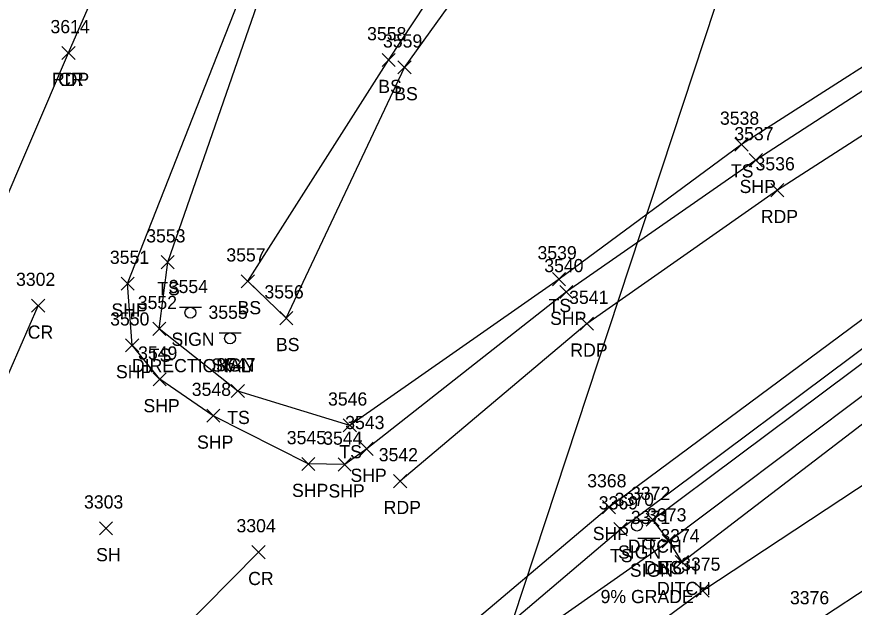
# Model space of a CAD drawing. Extents: x 1623612 to 1625808, y 621345 to 627748.
# Drawn here: x 1624984.7 to 1625111.7, y 626826.7 to 626916.3 of the extents above; entities that cross this region are included whole.
import ezdxf

# ---------------------------------------------------------------- set-up
doc = ezdxf.new("R2010")
doc.units = 0
for name, color, linetype in [('D_A', 7, 'Continuous'), ('D_I', 7, 'Continuous'), ('D_TIC', 7, 'Continuous'), ('DCP', 7, 'Continuous'), ('DD', 7, 'Continuous'), ('L_A', 7, 'Continuous'), ('L_I', 7, 'Continuous'), ('L_TIC', 7, 'Continuous'), ('LAWA', 7, 'Continuous'), ('LELB', 7, 'Continuous'), ('P_A', 7, 'Continuous'), ('P_I', 7, 'Continuous'), ('P_TIC', 7, 'Continuous'), ('PET', 7, 'Continuous'), ('PRC', 7, 'Continuous'), ('PSP', 7, 'Continuous'), ('S_A', 7, 'Continuous'), ('S_C', 7, 'Continuous'), ('S_I', 7, 'Continuous'), ('SSGN', 7, 'Continuous')]:
    doc.layers.add(name, color=color, linetype=linetype)

msp = doc.modelspace()

# ---------------------------------------------------------------- linework, layer by layer
at = {"layer": 'D_TIC'}
for points in [[(1625080.1, 626838.99), (1625082.1, 626840.99)], [(1625082.1, 626838.99), (1625080.1, 626840.99)], [(1625080.1, 626838.99), (1625082.1, 626840.99)], [(1625082.1, 626838.99), (1625080.1, 626840.99)], [(1625082.54, 626835.73), (1625084.54, 626837.73)], [(1625084.54, 626835.73), (1625082.54, 626837.73)], [(1625084.53, 626832.57), (1625086.53, 626834.57)], [(1625086.53, 626832.57), (1625084.53, 626834.57)]]:
    msp.add_lwpolyline(points, dxfattribs=at)
at = {"layer": 'DCP'}
msp.add_lwpolyline([(1625053.56, 626805.57), (1625095.39, 626932.35)], dxfattribs=at)
at = {"layer": 'DD'}
for points in [[(1625081.1, 626839.99), (1625120.07, 626869.1), (1625148.51, 626886.8), (1625173.75, 626902.4)], [(1625081.1, 626839.99), (1625083.54, 626836.73), (1625085.53, 626833.57), (1625123.95, 626862.95), (1625153.24, 626881.37), (1625160.13, 626885.56), (1625177.06, 626894.7), (1625176.09, 626897.9), (1625175.36, 626899.84), (1625173.75, 626902.4)]]:
    msp.add_lwpolyline(points, dxfattribs=at)
at = {"layer": 'L_TIC'}
for points in [[(1625040.06, 626908.7), (1625042.06, 626910.7)], [(1625042.06, 626908.7), (1625040.06, 626910.7)], [(1625042.48, 626907.59), (1625044.48, 626909.59)], [(1625044.48, 626907.59), (1625042.48, 626909.59)], [(1625093.57, 626895.89), (1625095.57, 626897.89)], [(1625095.57, 626895.89), (1625093.57, 626897.89)], [(1625006.56, 626878.04), (1625008.56, 626880.04)], [(1625008.56, 626878.04), (1625006.56, 626880.04)], [(1625018.71, 626875.15), (1625020.71, 626877.15)], [(1625020.71, 626875.15), (1625018.71, 626877.15)], [(1625065.91, 626875.48), (1625067.91, 626877.48)], [(1625067.91, 626875.48), (1625065.91, 626877.48)], [(1625024.54, 626869.55), (1625026.54, 626871.55)], [(1625026.54, 626869.55), (1625024.54, 626871.55)], [(1625024.54, 626869.55), (1625026.54, 626871.55)], [(1625026.54, 626869.55), (1625024.54, 626871.55)], [(1625005.28, 626867.94), (1625007.28, 626869.94)], [(1625007.28, 626867.94), (1625005.28, 626869.94)], [(1625017.18, 626858.5), (1625019.18, 626860.5)], [(1625019.18, 626858.5), (1625017.18, 626860.5)], [(1625034.19, 626853.3), (1625036.19, 626855.3)], [(1625036.19, 626853.3), (1625034.19, 626855.3)], [(1624997.21, 626837.69), (1624999.21, 626839.69)], [(1624999.21, 626837.69), (1624997.21, 626839.69)], [(1625075.24, 626837.55), (1625077.24, 626839.55)], [(1625077.24, 626837.55), (1625075.24, 626839.55)], [(1625082.54, 626835.73), (1625084.54, 626837.73)], [(1625084.54, 626835.73), (1625082.54, 626837.73)], [(1625087.69, 626828.26), (1625089.69, 626830.26)], [(1625089.69, 626828.26), (1625087.69, 626830.26)]]:
    msp.add_lwpolyline(points, dxfattribs=at)
at = {"layer": 'LAWA'}
msp.add_lwpolyline([(1625011.66, 626754.51), (1625041.42, 626781.36), (1625076.28, 626803.36), (1625105.24, 626824.17), (1625136.64, 626844.76), (1625156.9, 626876.93), (1625160.13, 626885.56)], dxfattribs=at)
at = {"layer": 'LELB'}
for points in [[(1625025.54, 626870.55), (1625019.71, 626876.15), (1625041.06, 626909.7), (1625061.93, 626941.31), (1625075.11, 626978.51), (1625096.76, 627007.08), (1625116.96, 627042.12), (1625139.15, 627072.88), (1625173.57, 627103.31), (1625198.3, 627138.01)], [(1625469.29, 627095.38), (1625429.94, 627072.01), (1625396.47, 627056.33), (1625363.17, 627036.91), (1625324.86, 627017.28), (1625282.83, 626996.93), (1625240.1, 626976.36), (1625200.92, 626956.72), (1625164.36, 626938.31), (1625128.12, 626918.34), (1625094.57, 626896.89), (1625066.91, 626876.48), (1625035.19, 626854.3), (1625018.18, 626859.5), (1625006.28, 626868.94), (1625007.56, 626879.04), (1625022.39, 626921.76), (1625036.67, 626956.96), (1625050.15, 626986.83), (1625070.28, 627027.73), (1625085.48, 627058.74), (1625111, 627101.13), (1625130.83, 627129.7)], [(1625025.54, 626870.55), (1625043.48, 626908.59), (1625065.43, 626939.12), (1625087.73, 626974.57), (1625090.56, 626979.87), (1625102.29, 627003.55)], [(1624803, 626375.22), (1624813.35, 626398.45), (1624825.59, 626427.7), (1624842.6, 626469.77), (1624853.82, 626508.25), (1624866.96, 626541.11), (1624879.6, 626570.92), (1624891.67, 626600.55), (1624909.69, 626627.37), (1624926.15, 626668.66), (1624945.08, 626696.18), (1624959.4, 626716.07), (1624979.06, 626741.61), (1624996.92, 626763.33), (1625023.93, 626790.77), (1625051.04, 626817.18), (1625076.24, 626838.55), (1625119.15, 626870.61), (1625147.29, 626888.18), (1625173.2, 626903.38), (1625206.27, 626920.6), (1625246.39, 626940.92)], [(1624810.6, 626380.38), (1624818.04, 626393.96), (1624831.09, 626425.55), (1624850.8, 626470.91), (1624859.76, 626506.71), (1624871.37, 626535.84), (1624886.95, 626567.84), (1624894.07, 626585.15), (1624895.49, 626590.47), (1624915.6, 626622.48), (1624934.63, 626664.39), (1624951.07, 626691.63), (1624965.13, 626713.06), (1624983.66, 626737.48), (1625004.4, 626758.94), (1625029.36, 626786.77), (1625054.16, 626807.16), (1625052.62, 626815.07), (1625083.54, 626836.73), (1625122.13, 626865.73), (1625150.08, 626884.49), (1625175.36, 626899.84), (1625209.28, 626915.51), (1625248.24, 626935.95)], [(1624815.3, 626378.44), (1624822.97, 626393.02), (1624835.07, 626424.21), (1624854.93, 626470.78), (1624864.02, 626503.22), (1624876, 626534.5), (1624889.39, 626566.85), (1624897.36, 626584.29), (1624900.1, 626587.8), (1624917.68, 626620.81), (1624936.92, 626663.47), (1624953.32, 626690.33), (1624968.57, 626711.23), (1624977.21, 626720.96), (1624986.38, 626735.04), (1625009.06, 626756.63), (1625033.16, 626784.59), (1625055.85, 626805.24), (1625057.84, 626806.47), (1625088.69, 626829.26), (1625128.34, 626855.41), (1625156.9, 626876.93)]]:
    msp.add_lwpolyline(points, dxfattribs=at)
at = {"layer": 'P_TIC'}
for points in [[(1624991.52, 626909.77), (1624993.52, 626911.77)], [(1624993.52, 626909.77), (1624991.52, 626911.77)], [(1624991.52, 626909.77), (1624993.52, 626911.77)], [(1624993.52, 626909.77), (1624991.52, 626911.77)], [(1625095.75, 626893.53), (1625097.75, 626895.53)], [(1625097.75, 626893.53), (1625095.75, 626895.53)], [(1625099.02, 626888.97), (1625101.02, 626890.97)], [(1625101.02, 626888.97), (1625099.02, 626890.97)], [(1625000.48, 626874.79), (1625002.48, 626876.79)], [(1625002.48, 626874.79), (1625000.48, 626876.79)], [(1625067.02, 626873.53), (1625069.02, 626875.53)], [(1625069.02, 626873.53), (1625067.02, 626875.53)], [(1624986.9, 626871.45), (1624988.9, 626873.45)], [(1624988.9, 626871.45), (1624986.9, 626873.45)], [(1625070.13, 626868.72), (1625072.13, 626870.72)], [(1625072.13, 626868.72), (1625070.13, 626870.72)], [(1625001.17, 626865.44), (1625003.17, 626867.44)], [(1625003.17, 626865.44), (1625001.17, 626867.44)], [(1625005.34, 626860.28), (1625007.34, 626862.28)], [(1625007.34, 626860.28), (1625005.34, 626862.28)], [(1625013.47, 626854.76), (1625015.47, 626856.76)], [(1625015.47, 626854.76), (1625013.47, 626856.76)], [(1625036.74, 626849.73), (1625038.74, 626851.73)], [(1625038.74, 626849.73), (1625036.74, 626851.73)], [(1625027.88, 626847.44), (1625029.88, 626849.44)], [(1625029.88, 626847.44), (1625027.88, 626849.44)], [(1625033.4, 626847.36), (1625035.4, 626849.36)], [(1625035.4, 626847.36), (1625033.4, 626849.36)], [(1625041.82, 626844.85), (1625043.82, 626846.85)], [(1625043.82, 626844.85), (1625041.82, 626846.85)], [(1625073.48, 626840.9), (1625075.48, 626842.9)], [(1625075.48, 626840.9), (1625073.48, 626842.9)], [(1625020.33, 626834.08), (1625022.33, 626836.08)], [(1625022.33, 626834.08), (1625020.33, 626836.08)]]:
    msp.add_lwpolyline(points, dxfattribs=at)
at = {"layer": 'PET'}
for points in [[(1624992.52, 626910.77), (1625008.6, 626947.6), (1625024.83, 626984.16), (1625042.83, 627020.47), (1625062.51, 627057.29), (1625085.4, 627094.25), (1625110.27, 627129.17)], [(1625473.25, 627090.09), (1625432.8, 627065.24), (1625401.59, 627047.56), (1625365.67, 627029.01), (1625328.14, 627010.31), (1625285.33, 626989.61), (1625243.69, 626969.41), (1625203.66, 626950.01), (1625167.56, 626931.17), (1625131.52, 626910.23), (1625100.02, 626889.97), (1625071.13, 626869.72), (1625042.82, 626845.85)]]:
    msp.add_lwpolyline(points, dxfattribs=at)
at = {"layer": 'PRC'}
for points in [[(1624958.48, 626830.64), (1624976.06, 626872.54), (1624992.52, 626910.77)], [(1624873.9, 626593.46), (1624883.54, 626618.76), (1624893.81, 626643.76), (1624908.18, 626679.39), (1624921.64, 626711.58), (1624936.31, 626747.99), (1624947.72, 626775.53), (1624957.85, 626801.45), (1624972.86, 626837.96), (1624987.9, 626872.45)], [(1625021.33, 626835.08), (1624996.64, 626810.12), (1624971.37, 626780.31), (1624950.14, 626748.77)]]:
    msp.add_lwpolyline(points, dxfattribs=at)
at = {"layer": 'PSP'}
for points in [[(1625241.24, 626974.73), (1625201.61, 626954.83), (1625165.46, 626936.02), (1625129.49, 626915.73), (1625096.75, 626894.53), (1625068.02, 626874.53), (1625037.74, 626850.73), (1625034.4, 626848.36), (1625028.88, 626848.44), (1625014.47, 626855.76), (1625006.34, 626861.28), (1625002.17, 626866.44), (1625001.48, 626875.79), (1625020.05, 626923.14), (1625034.42, 626958.47), (1625047.14, 626987.9), (1625066.83, 627030.1), (1625082.81, 627060.49), (1625108.38, 627102.81), (1625128.19, 627131.96)], [(1624794.65, 626368.04), (1624800.63, 626383.44), (1624817.3, 626423.08), (1624832.73, 626462.11), (1624850.47, 626510.04), (1624865.43, 626546.52), (1624882.91, 626590.11), (1624893.72, 626613.2), (1624905.71, 626637.22), (1624924.51, 626670), (1624942.43, 626698.12), (1624956.64, 626717.85), (1624976.67, 626743.84), (1624995.18, 626765.37), (1625020.7, 626793.24), (1625048.65, 626820.06), (1625074.48, 626841.9), (1625117.11, 626873.56), (1625144.96, 626891.32), (1625172.26, 626906.31), (1625205.02, 626923.68), (1625245.42, 626943.67)]]:
    msp.add_lwpolyline(points, dxfattribs=at)
at = {"layer": 'SSGN'}
for p, q in [((1625009.35, 626872.21), (1625012.68, 626872.21)), ((1625011, 626871.38), (1625011, 626871.38)), ((1625015.37, 626868.31), (1625018.71, 626868.31)), ((1625017.02, 626867.48), (1625017.02, 626867.48)), ((1625077.07, 626839.94), (1625080.41, 626839.94)), ((1625078.72, 626839.11), (1625078.72, 626839.11)), ((1625078.86, 626837.2), (1625082.2, 626837.2)), ((1625080.51, 626836.36), (1625080.51, 626836.36))]:
    msp.add_line(p, q, dxfattribs=at)
for centre in [(1625011, 626871.38), (1625017.02, 626867.48), (1625078.72, 626839.11), (1625080.51, 626836.36)]:
    msp.add_circle(centre, 0.833, dxfattribs=at)

# ---------------------------------------------------------------- texts
at = {"layer": 'D_A'}
for p in [(1625077.34, 626834.99), (1625077.34, 626834.99), (1625079.78, 626831.73), (1625081.77, 626828.57)]:
    msp.add_text('DITCH', height=2, dxfattribs=at).set_placement(p)
at = {"layer": 'D_I'}
for s, p in [('3372', (1625077.84, 626842.99)), ('3372', (1625077.84, 626842.99)), ('3373', (1625080.28, 626839.73)), ('3374', (1625082.27, 626836.57))]:
    msp.add_text(s, height=2, dxfattribs=at).set_placement(p)
at = {"layer": 'L_A'}
for s, p in [('BS', (1625039.5, 626904.7)), ('BS', (1625041.92, 626903.59)), ('TS', (1625092.97, 626891.89)), ('TS', (1625005.97, 626874.04)), ('BS', (1625018.15, 626871.15)), ('TS', (1625065.32, 626871.48)), ('BS', (1625023.98, 626865.55)), ('BS', (1625023.98, 626865.55)), ('TS', (1625004.69, 626863.94)), ('TS', (1625016.59, 626854.5)), ('TS', (1625033.6, 626849.3)), ('SH', (1624996.7, 626833.69)), ('TS', (1625074.65, 626833.55)), ('BS', (1625081.98, 626831.73))]:
    msp.add_text(s, height=2, dxfattribs=at).set_placement(p)
at = {"layer": 'L_I'}
for s, p in [('3558', (1625037.8, 626912.7)), ('3559', (1625040.21, 626911.59)), ('3538', (1625091.31, 626899.89)), ('3553', (1625004.3, 626882.04)), ('3539', (1625063.64, 626879.48)), ('3557', (1625016.45, 626879.15)), ('3556', (1625022.23, 626873.55)), ('3556', (1625022.23, 626873.55)), ('3552', (1625003.02, 626871.94)), ('3547', (1625014.92, 626862.5)), ('3546', (1625031.87, 626857.3)), ('3303', (1624994.87, 626841.69)), ('3369', (1625072.93, 626841.55)), ('3373', (1625080.28, 626839.73)), ('3375', (1625085.43, 626832.26)), ('3376', (1625101.93, 626827.17))]:
    msp.add_text(s, height=2, dxfattribs=at).set_placement(p)
at = {"layer": 'P_A'}
for s, p in [('RDP', (1624990, 626905.77)), ('CR', (1624990.95, 626905.77)), ('SHP', (1625094.29, 626889.53)), ('RDP', (1625097.51, 626884.97)), ('SHP', (1624999.02, 626870.79)), ('SHP', (1625065.55, 626869.53)), ('CR', (1624986.33, 626867.45)), ('RDP', (1625068.62, 626864.72)), ('SHP', (1624999.71, 626861.44)), ('SHP', (1625003.88, 626856.28)), ('SHP', (1625012.01, 626850.76)), ('SHP', (1625035.28, 626845.73)), ('SHP', (1625026.41, 626843.44)), ('SHP', (1625031.94, 626843.36)), ('RDP', (1625040.31, 626840.85)), ('SHP', (1625072.02, 626836.9)), ('CR', (1625019.76, 626830.08))]:
    msp.add_text(s, height=2, dxfattribs=at).set_placement(p)
at = {"layer": 'P_I'}
for s, p in [('3614', (1624989.78, 626913.77)), ('3614', (1624989.78, 626913.77)), ('3537', (1625093.49, 626897.53)), ('3536', (1625096.71, 626892.97)), ('3551', (1624998.79, 626878.79)), ('3540', (1625064.67, 626877.53)), ('3302', (1624984.56, 626875.45)), ('3541', (1625068.44, 626872.72)), ('3550', (1624998.83, 626869.44)), ('3549', (1625003.07, 626864.28)), ('3548', (1625011.21, 626858.76)), ('3543', (1625034.48, 626853.73)), ('3545', (1625025.62, 626851.44)), ('3544', (1625031.14, 626851.36)), ('3542', (1625039.56, 626848.85)), ('3368', (1625071.18, 626844.9)), ('3304', (1625017.99, 626838.08))]:
    msp.add_text(s, height=2, dxfattribs=at).set_placement(p)
at = {"layer": 'S_A'}
for p in [(1625008.13, 626866.36), (1625014.16, 626862.46), (1625075.86, 626834.09), (1625077.65, 626831.34)]:
    msp.add_text('SIGN', height=2, dxfattribs=at).set_placement(p)
at = {"layer": 'S_C'}
for s, p in [('DIRECTIONAL', (1625002.14, 626862.36)), ('9% GRADE', (1625073.21, 626827.34))]:
    msp.add_text(s, height=2, dxfattribs=at).set_placement(p)
at = {"layer": 'S_I'}
for s, p in [('3554', (1625007.72, 626874.36)), ('3555', (1625013.74, 626870.46)), ('3370', (1625075.35, 626842.09)), ('3371', (1625077.8, 626839.34))]:
    msp.add_text(s, height=2, dxfattribs=at).set_placement(p)

doc.saveas('drawing.dxf')
